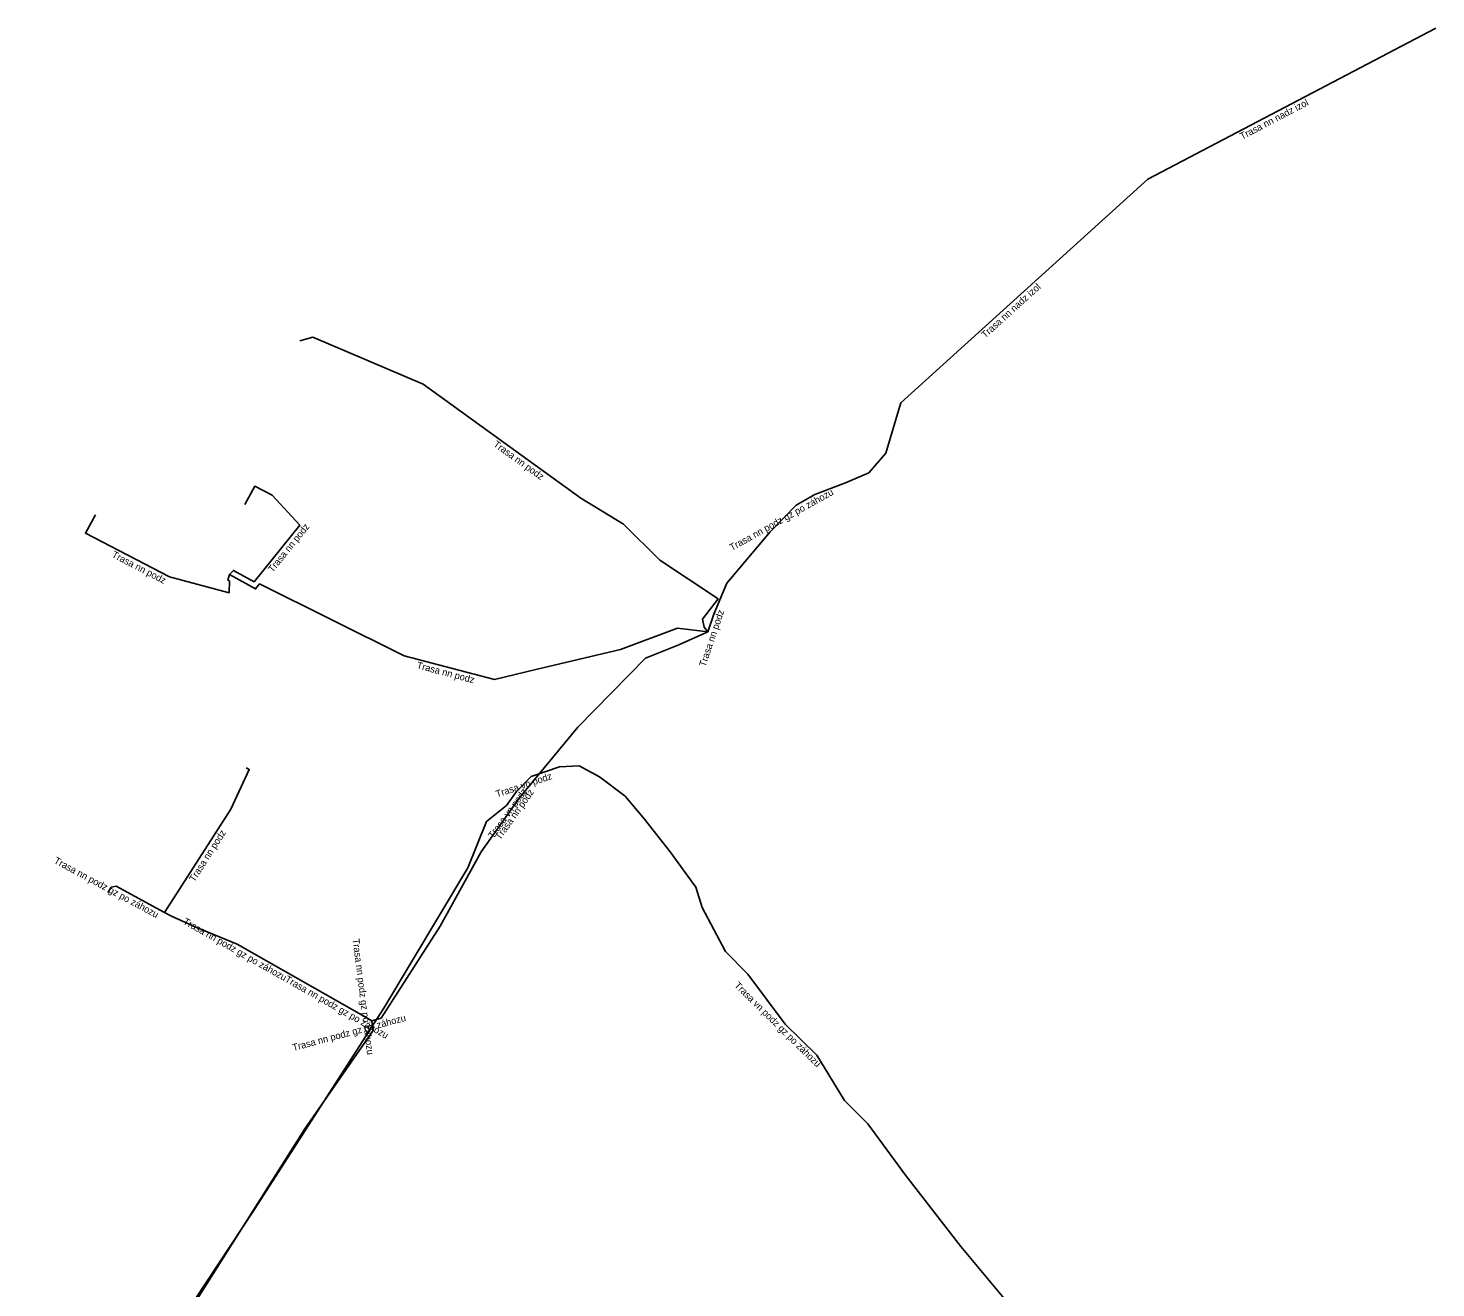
# Model space of a CAD drawing. Extents: x -528089 to -527692, y -1079306 to -1078676.
# Drawn here: x -527901 to -527799.5, y -1078767.2 to -1078676.3 of the extents above; entities that cross this region are included whole.
import ezdxf

# ---------------------------------------------------------------- set-up
doc = ezdxf.new("R2010")
doc.units = 0
for name, color, linetype in [('Popiskový text - Ostatní atributy Trasy', 7, 'Continuous'), ('Spojnice NN', 7, 'Continuous'), ('Spojnice VN', 7, 'Continuous')]:
    doc.layers.add(name, color=color, linetype=linetype)

msp = doc.modelspace()

# ---------------------------------------------------------------- linework, layer by layer
at = {"layer": 'Spojnice NN'}
for points in [[(-527820.3, -1078687.22), (-527799.54, -1078676.33)], [(-527838.12, -1078703.36), (-527820.3, -1078687.22)], [(-527852.02, -1078719.87), (-527852.28, -1078719.53), (-527852.42, -1078718.95), (-527851.28, -1078717.48), (-527855.48, -1078714.69), (-527858.11, -1078712.11), (-527861.19, -1078710.22), (-527872.54, -1078702.01), (-527880.5, -1078698.62), (-527881.44, -1078698.87)], [(-527851.59, -1078718.6), (-527850.66, -1078716.36), (-527847.54, -1078712.65), (-527845.66, -1078710.72), (-527844.31, -1078709.97), (-527842.11, -1078709.11), (-527840.42, -1078708.41), (-527839.19, -1078706.99), (-527838.48, -1078704.55), (-527838.12, -1078703.36)], [(-527885.41, -1078710.67), (-527884.69, -1078709.37), (-527883.44, -1078710), (-527881.44, -1078712.17), (-527884.73, -1078716.25), (-527886.22, -1078715.43), (-527886.5, -1078715.74)], [(-527896.16, -1078711.42), (-527896.89, -1078712.76), (-527890.83, -1078715.9), (-527886.52, -1078717.04), (-527886.51, -1078716.19), (-527886.62, -1078716.13), (-527886.5, -1078715.74)], [(-527886.5, -1078715.74), (-527884.63, -1078716.77), (-527884.34, -1078716.41), (-527873.91, -1078721.59), (-527867.41, -1078723.31), (-527864.43, -1078722.59), (-527858.33, -1078721.13), (-527854.2, -1078719.6), (-527852.02, -1078719.87)], [(-527852.02, -1078719.87), (-527851.59, -1078718.6)], [(-527852.02, -1078719.87), (-527854.11, -1078720.79), (-527856.51, -1078721.76), (-527861.4, -1078726.73), (-527865.63, -1078731.85), (-527868.37, -1078735.73), (-527871.32, -1078741.1), (-527875.57, -1078747.73)], [(-527885.3, -1078729.68), (-527885.08, -1078729.79), (-527886.41, -1078732.64), (-527891.19, -1078740.1)], [(-527895.27, -1078738.67), (-527895.03, -1078738.28), (-527894.69, -1078738.21), (-527891.19, -1078740.1)], [(-527891.19, -1078740.1), (-527890.68, -1078740.37), (-527888.94, -1078741.15), (-527885.95, -1078742.39), (-527877.15, -1078747.39)], [(-527877.15, -1078747.39), (-527876.24, -1078747.91)], [(-527876.24, -1078747.91), (-527875.57, -1078747.73)], [(-527876.15, -1078748.62), (-527881.08, -1078755.7), (-527890.34, -1078770.34), (-527895.52, -1078778.72), (-527901.44, -1078788.43), (-527903.84, -1078793.06), (-527907.78, -1078799.52), (-527916.61, -1078814.71), (-527917.06, -1078816.84), (-527919.98, -1078822.17), (-527924.47, -1078829.21), (-527929.52, -1078839.3), (-527933.49, -1078846.02), (-527936.34, -1078852.24), (-527940.87, -1078863.22), (-527944.75, -1078870.23), (-527946.26, -1078873.7), (-527951.36, -1078883.98), (-527955.3, -1078891.37), (-527954.1, -1078893.05), (-527952.62, -1078893.82), (-527950.35, -1078896.83)], [(-527876.24, -1078747.91), (-527876.15, -1078748.62)]]:
    msp.add_lwpolyline(points, dxfattribs=at)
at = {"layer": 'Spojnice VN'}
for points in [[(-527862.71, -1078729.61), (-527864.75, -1078730.3), (-527865.82, -1078731.37)], [(-527828.12, -1078770.85), (-527829.58, -1078769.24), (-527833.78, -1078764.19), (-527837.77, -1078759.04), (-527840.48, -1078755.33), (-527842.17, -1078753.66), (-527844.16, -1078750.39), (-527846.44, -1078748.15), (-527849.13, -1078744.56), (-527850.75, -1078742.92), (-527852.43, -1078739.74), (-527852.88, -1078738.27), (-527854.74, -1078735.73), (-527856.58, -1078733.37), (-527857.98, -1078731.72), (-527859.83, -1078730.33), (-527861.31, -1078729.53), (-527862.71, -1078729.61)], [(-527865.82, -1078731.37), (-527866.55, -1078732.38)], [(-527950.35, -1078896.83), (-527953.4, -1078892.8), (-527953.13, -1078886.8), (-527946.25, -1078873.1), (-527936.41, -1078852.32), (-527930.88, -1078841.27), (-527920.34, -1078822.02), (-527916.96, -1078814.57), (-527906.15, -1078795.86), (-527889.87, -1078769.33), (-527884.73, -1078761.54), (-527875.38, -1078747), (-527869.33, -1078736.87), (-527867.99, -1078733.54), (-527866.55, -1078732.38)], [(-527950.35, -1078896.83), (-527953.4, -1078892.8), (-527953.13, -1078886.8), (-527946.25, -1078873.1), (-527936.41, -1078852.32), (-527930.88, -1078841.27), (-527920.34, -1078822.02), (-527916.96, -1078814.57), (-527906.15, -1078795.86), (-527889.87, -1078769.33), (-527884.73, -1078761.54), (-527875.38, -1078747), (-527869.33, -1078736.87), (-527867.99, -1078733.54), (-527866.55, -1078732.38)]]:
    msp.add_lwpolyline(points, dxfattribs=at)

# ---------------------------------------------------------------- texts
at = {"layer": 'Popiskový text - Ostatní atributy Trasy'}
for s, rotation, p in [('Trasa nn nadz izol', 27.666, (-527813.51, -1078684.39)), ('Trasa nn nadz izol', 42.1767, (-527832.03, -1078698.72)), ('Trasa nn podz', 324.12, (-527867.53, -1078706.44)), ('Trasa nn podz gz po záhozu', 29.0546, (-527850.29, -1078714.04)), ('Trasa nn podz', 51.1542, (-527883.39, -1078715.62)), ('Trasa nn podz', 332.609, (-527895.04, -1078714.45)), ('Trasa nn podz', 71.2948, (-527852.2, -1078722.42)), ('Trasa nn podz', 345.1784, (-527873.05, -1078722.49)), ('Trasa vn podz', 18.6874, (-527867.22, -1078731.82)), ('Trasa vn podz', 54.1416, (-527867.5, -1078734.81)), ('Trasa nn podz', 54.7708, (-527866.99, -1078734.91)), ('Trasa nn podz', 57.3503, (-527889.04, -1078737.94)), ('Trasa nn podz gz po záhozu', 331.631, (-527899.21, -1078736.51)), ('Trasa nn podz gz po záhozu', 330.3825, (-527889.9, -1078740.89)), ('Trasa nn podz gz po záhozu', 277.2243, (-527877.64, -1078742.02)), ('Trasa nn podz gz po záhozu', 330.3813, (-527882.56, -1078745.06)), ('Trasa vn podz gz po záhozu', 315.507, (-527850.15, -1078745.41)), ('Trasa nn podz gz po záhozu', 15.0378, (-527881.9, -1078750.1))]:
    msp.add_text(s, height=0.5, rotation=rotation, dxfattribs=at).set_placement(p)

doc.saveas('drawing.dxf')
